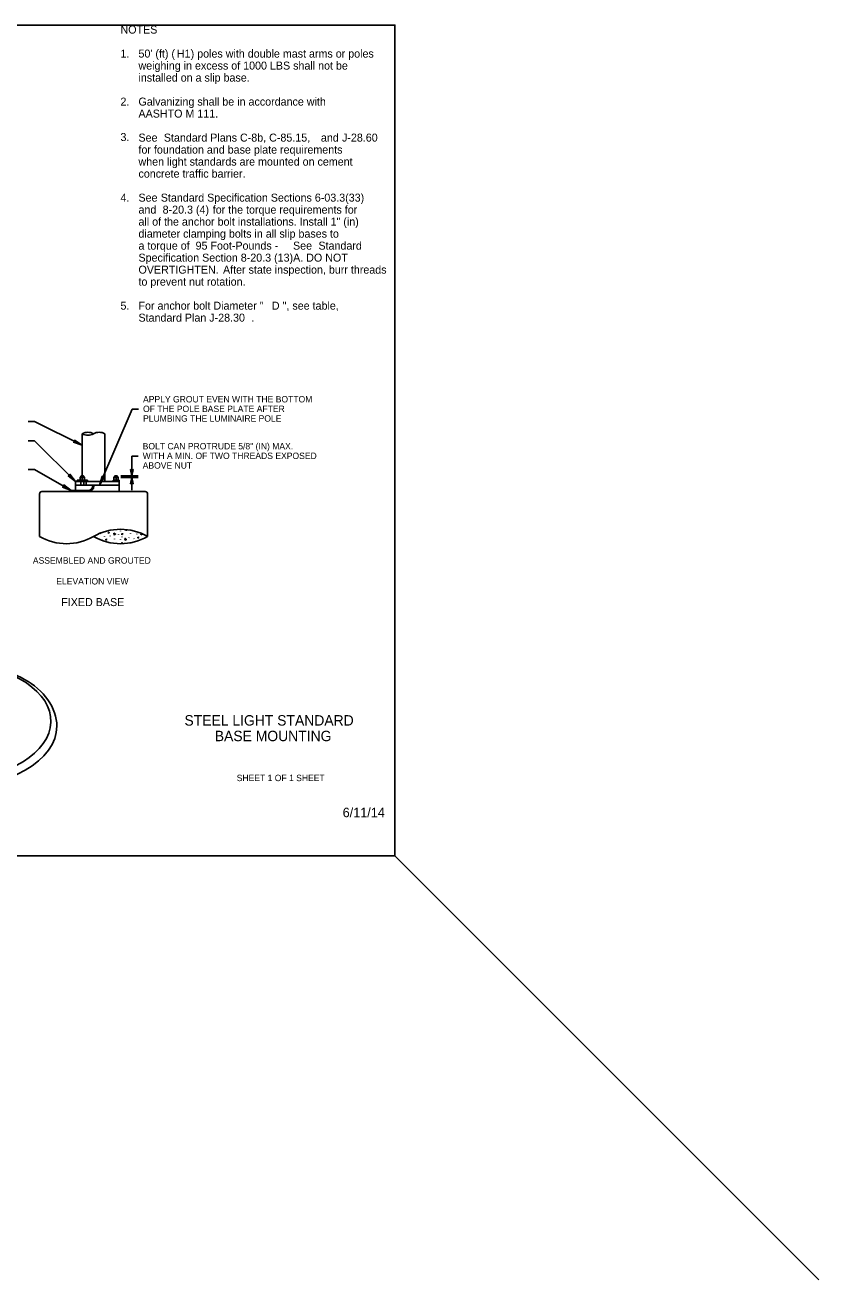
# Model space of a CAD drawing. Extents: x 99862 to 104211, y 98939 to 102076.
# Drawn here: x 102226 to 104211, y 98939 to 102076 of the extents above; entities that cross this region are included whole.
import ezdxf

# ---------------------------------------------------------------- set-up
doc = ezdxf.new("R2010")
doc.units = 0
for name, color, linetype in [('Level 1', 7, 'Continuous'), ('Level 11', 7, 'Continuous'), ('Level 12', 7, 'Continuous'), ('Level 15', 7, 'Continuous'), ('Level 16', 7, 'Continuous'), ('Level 20', 7, 'Continuous'), ('Level 60', 7, 'Continuous'), ('Level 62', 7, 'Continuous'), ('Level 7', 7, 'Continuous'), ('Level 8', 7, 'Continuous'), ('Level 9', 7, 'Continuous')]:
    doc.layers.add(name, color=color, linetype=linetype)

msp = doc.modelspace()

# ---------------------------------------------------------------- linework, layer by layer
at = {"layer": 'Level 1'}
msp.add_line((103150, 100000), (104210.7, 98939.3), dxfattribs=at)
msp.add_lwpolyline([(99862, 99999.5), (103151, 99999.5), (103151, 102075.5), (99862, 102075.5)], close=True, dxfattribs=at)
for centre, radius, start, end in [((102383.5, 101029.8), 28.1, 60, 120), ((102383.5, 101078.5), 28.1, 240, 300), ((102411.6, 101029.8), 28.1, 60, 120), ((102330, 100914.3), 135, 240, 300), ((102465, 100680.5), 135, 60, 120), ((102465, 100914.3), 135, 240, 300)]:
    msp.add_arc(centre, radius, start, end, dxfattribs=at)
at = {"layer": 'Level 11'}
for p, q in [((102356.7, 100934.7), (102356.7, 100938.4)), ((102356.7, 100938.4), (102374.6, 100938.4)), ((102356.7, 100934.7), (102374.6, 100934.7)), ((102374.6, 100938.4), (102382.1, 100938.4)), ((102374.6, 100934.7), (102374.6, 100938.4)), ((102374.6, 100934.7), (102375.2, 100934.7)), ((102382.1, 100934.7), (102382.1, 100938.4)), ((102446.3, 100938.4), (102461.3, 100938.4)), ((102446.3, 100934.7), (102446.3, 100938.4)), ((102461.3, 100934.7), (102461.3, 100938.4))]:
    msp.add_line(p, q, dxfattribs=at)
at = {"layer": 'Level 12'}
msp.add_lwpolyline([(102396.1, 100925.3), (102378.8, 100925.3), (102373.2, 100925.3), (102365.7, 100925.3), (102352.5, 100925.3), (102352.5, 100909.4), (102461.3, 100909.4), (102461.3, 100925.3), (102396.1, 100925.3)], dxfattribs=at)
for centre, major_axis, start_param, end_param in [((102035.9, 100335.8), (-255, 0), 4.934807, 10.773157), ((102035.9, 100323.6), (-270, 0), 6.283185, 9.424762)]:
    msp.add_ellipse(centre, major_axis=major_axis, ratio=0.57735, start_param=start_param, end_param=end_param, dxfattribs=at)
msp.add_open_spline([(102305.9, 100323.6), (102305.9, 100345.1), (102289.9, 100392.8), (102227.3, 100444.3), (102152.7, 100472), (102109.3, 100480.1), (102092.1, 100482.3)], degree=3, dxfattribs=at)
at = {"layer": 'Level 15'}
for p, q in [((102412.7, 100925.3), (102494.2, 101115.8)), ((102510.2, 101115.8), (102494.2, 101115.8)), ((102250.4, 101084.5), (102234.4, 101084.5)), ((102369.4, 101025.2), (102250.4, 101084.5)), ((102250.4, 101036.5), (102234.4, 101036.5)), ((102352.5, 100934.7), (102250.4, 101036.5)), ((102493.3, 100948.8), (102493.3, 100998.4)), ((102493.3, 100998.4), (102509.3, 100998.4)), ((102234.4, 100964.8), (102250.4, 100964.8)), ((102341.4, 100912.2), (102250.4, 100964.8)), ((102465.5, 100948.8), (102509.3, 100948.8)), ((102465.5, 100945), (102509.3, 100945)), ((102493.3, 100913), (102493.3, 100945))]:
    msp.add_line(p, q, dxfattribs=at)
for points in [[(102369.4, 101025.2), (102347.7, 101032.7), (102349.9, 101034.9), (102350.3, 101038)], [(102493.3, 100948.8), (102490.2, 100964.5), (102493.3, 100963.8), (102496.4, 100964.5)], [(102341.4, 100912.2), (102320.1, 100921), (102322.5, 100923.1), (102323.1, 100926.2)], [(102352.5, 100934.7), (102334.3, 100948.7), (102337.1, 100950.1), (102338.5, 100952.9)], [(102412.7, 100925.3), (102418.9, 100947.5), (102421.3, 100945.3), (102424.4, 100945.1)], [(102493.3, 100945), (102490.2, 100929.3), (102493.3, 100930), (102496.4, 100929.3)]]:
    msp.add_lwpolyline(points, close=True, dxfattribs=at)
at = {"layer": 'Level 16'}
for p, q in [((102425, 100796.8), (102425.1, 100797.7)), ((102439, 100797.8), (102439.1, 100798.7)), ((102459.7, 100802.6), (102460, 100801.8)), ((102465.2, 100810.7), (102465.3, 100811.6)), ((102468, 100796.9), (102468.5, 100796.5)), ((102468.4, 100796.8), (102468.9, 100796.4)), ((102479.2, 100811.6), (102479.3, 100812.5)), ((102490.2, 100804.5), (102490.3, 100805.4)), ((102505.4, 100802.8), (102505.5, 100803.7)), ((102419.4, 100788.7), (102419.8, 100788)), ((102446.1, 100781.1), (102446.1, 100781.1)), ((102450, 100790.7), (102450, 100791.6)), ((102465.2, 100789), (102465.3, 100789.8)), ((102486.2, 100794), (102486.3, 100794.9)), ((102498.5, 100792.3), (102499.1, 100791.9))]:
    msp.add_line(p, q, dxfattribs=at)
for points in [[(102415.5, 100805.7), (102414.2, 100804.7)], [(102414.2, 100804.7), (102414.2, 100805.2)], [(102434.6, 100805), (102434.9, 100807.4), (102437, 100806.8), (102434.6, 100805)], [(102449.5, 100800.4), (102448.5, 100805.5), (102452.6, 100803.4), (102449.6, 100800.5)], [(102468.5, 100801.9), (102468.7, 100804.4), (102470.8, 100803.7), (102468.5, 100801.9)], [(102515.9, 100801.7), (102516.4, 100805.1)], [(102519.7, 100803.5), (102519.8, 100803.4), (102515.9, 100801.7)], [(102428.2, 100788.1), (102428.5, 100790.5), (102430.6, 100789.8), (102428.2, 100788.1)], [(102467.9, 100779.7), (102468.2, 100781.7), (102470.3, 100781), (102468.6, 100779.8)], [(102475.6, 100787.9), (102476.4, 100792.9), (102479.6, 100789.6), (102475.7, 100787.9)], [(102488.6, 100781.8), (102488.6, 100782.1), (102489.2, 100781.9)], [(102508.1, 100793.1), (102508.4, 100795.6), (102510.5, 100794.9), (102508.1, 100793.1)], [(102528.8, 100795.5), (102528.9, 100795.9), (102529.4, 100795.7)]]:
    msp.add_lwpolyline(points, dxfattribs=at)
at = {"layer": 'Level 60'}
msp.add_line((103151, 102075.5), (103151, 102075.5), dxfattribs=at)
at = {"layer": 'Level 62'}
for points in [[(102366, 100934.7), (102365.7, 100934.7), (102365.6, 100934.6), (102365.7, 100934.6)], [(102365.7, 100947.1), (102365.7, 100947.1), (102365.7, 100947.1), (102365.7, 100947.1)], [(102365.7, 100945.9), (102365.7, 100945.9), (102365.7, 100945.9), (102365.7, 100945.8)]]:
    msp.add_open_spline(points, degree=3, dxfattribs=at)
at = {"layer": 'Level 7'}
for p, q in [((102356.1, 100934.7), (102356.7, 100934.7)), ((102375.2, 100934.7), (102378.8, 100934.7))]:
    msp.add_line(p, q, dxfattribs=at)
at = {"layer": 'Level 8'}
for p, q in [((102369.4, 101054.1), (102369.4, 100948.8)), ((102425.7, 100934.7), (102425.7, 101054.1)), ((102352.5, 100925.3), (102352.5, 100934.7)), ((102352.5, 100934.7), (102356.1, 100934.7)), ((102352.5, 100925.3), (102461.3, 100925.3)), ((102352.5, 100909.4), (102352.5, 100925.3)), ((102378.8, 100934.7), (102461.3, 100934.7)), ((102378.8, 100925.3), (102378.8, 100934.7)), ((102461.3, 100925.3), (102461.3, 100934.7)), ((102461.3, 100909.4), (102461.3, 100925.3)), ((102262.5, 100903.8), (102262.5, 100797.4)), ((102268.2, 100909.4), (102526.9, 100909.4)), ((102341.4, 100909.4), (102341.4, 100912.2)), ((102341.4, 100912.2), (102352.5, 100912.2)), ((102352.5, 100912.2), (102383, 100912.2)), ((102352.5, 100909.4), (102383, 100909.4)), ((102532.5, 100797.4), (102532.5, 100903.8))]:
    msp.add_line(p, q, dxfattribs=at)
for centre, radius, start, end in [((102383, 100925.3), 13.1, 270.0006, 360), ((102383, 100925.3), 15.9, 269.9997, 360), ((102268.2, 100903.8), 5.62, 90, 180), ((102526.9, 100903.8), 5.62, 0, 90)]:
    msp.add_arc(centre, radius, start, end, dxfattribs=at)
at = {"layer": 'Level 9'}
for p, q in [((102366.5, 100945), (102363.8, 100945)), ((102363.8, 100944.5), (102363.8, 100938.4)), ((102366.3, 100948.8), (102365.7, 100948.1)), ((102365.7, 100948.1), (102365.7, 100945)), ((102373.2, 100948.1), (102365.7, 100948.1)), ((102365.7, 100934.7), (102365.7, 100925.3)), ((102372.5, 100948.8), (102366.3, 100948.8)), ((102366.7, 100945), (102366.5, 100945)), ((102372.1, 100945), (102366.7, 100945)), ((102369.4, 100944.5), (102369.4, 100938.4)), ((102372.3, 100945), (102372.1, 100945)), ((102375, 100945), (102372.3, 100945)), ((102373.2, 100948.1), (102372.5, 100948.8)), ((102373.2, 100945), (102373.2, 100948.1)), ((102373.2, 100925.3), (102373.2, 100934.7)), ((102375, 100944.5), (102375, 100938.4)), ((102450.9, 100945), (102448.2, 100945)), ((102448.2, 100944.5), (102448.2, 100938.4)), ((102450.7, 100948.8), (102450, 100948.1)), ((102450, 100948.1), (102450, 100945)), ((102457.5, 100948.1), (102450, 100948.1)), ((102456.9, 100948.8), (102450.7, 100948.8)), ((102451.1, 100945), (102450.9, 100945)), ((102456.5, 100945), (102451.1, 100945)), ((102453.8, 100944.5), (102453.8, 100938.4)), ((102456.7, 100945), (102456.5, 100945)), ((102459.4, 100945), (102456.7, 100945)), ((102457.5, 100948.1), (102456.9, 100948.8)), ((102457.5, 100945), (102457.5, 100948.1)), ((102459.4, 100944.5), (102459.4, 100938.4))]:
    msp.add_line(p, q, dxfattribs=at)
for points in [[(102363.8, 100944.5), (102363.8, 100944.8), (102363.8, 100945), (102363.8, 100945)], [(102366.5, 100945), (102365.6, 100945), (102364.7, 100944.8), (102363.8, 100944.5)], [(102369.4, 100944.5), (102368.5, 100944.8), (102367.7, 100945), (102366.7, 100945)], [(102372.1, 100945), (102371.2, 100945), (102370.3, 100944.8), (102369.4, 100944.5)], [(102375, 100944.5), (102374.2, 100944.8), (102373.3, 100945), (102372.3, 100945)], [(102375, 100945), (102375, 100945), (102375, 100945), (102375, 100945)], [(102375, 100944.5), (102375, 100944.8), (102375, 100945), (102375, 100945)], [(102448.2, 100944.5), (102448.2, 100944.8), (102448.2, 100945), (102448.2, 100945)], [(102450.9, 100945), (102449.9, 100945), (102449, 100944.8), (102448.2, 100944.5)], [(102453.8, 100944.5), (102452.9, 100944.8), (102452, 100945), (102451.1, 100945)], [(102456.5, 100945), (102455.6, 100945), (102454.7, 100944.8), (102453.8, 100944.5)], [(102459.4, 100944.5), (102458.5, 100944.8), (102457.6, 100945), (102456.7, 100945)], [(102459.4, 100945), (102459.4, 100945), (102459.4, 100945), (102459.4, 100945)], [(102459.4, 100944.5), (102459.4, 100944.8), (102459.4, 100945), (102459.4, 100945)]]:
    msp.add_open_spline(points, degree=2, dxfattribs=at)

# ---------------------------------------------------------------- texts
at = {"layer": 'Level 1'}
msp.add_text('6/11/14', height=23.62, dxfattribs=at).set_placement((103020.3, 100095.8))
at = {"layer": 'Level 20'}
for s, height, p in [('NOTES', 20, (102464.9, 102054.3)), ('1.', 20, (102464.9, 101994.3)), ("50' (ft) (", 20, (102509.9, 101994.3)), ('H1', 20, (102605.6, 101994.3)), (') poles with double mast arms or poles', 20, (102640.3, 101994.3)), ('weighing in excess of 1000 LBS shall not be', 20, (102509.9, 101964.3)), ('installed on a slip base.', 20, (102509.9, 101934.3)), ('2.', 20, (102464.9, 101874.3)), ('Galvanizing shall be in accordance with', 20, (102509.9, 101874.3)), ('AASHTO M 111.', 20, (102509.9, 101844.3)), ('3.', 20, (102464.9, 101785.7)), ('See ', 20, (102509.9, 101784.3)), ('Standard Plans C-8b, C-85.15, ', 20, (102573.3, 101784.3)), ('and', 20, (102965.9, 101784.3)), (' J-28.60 ', 20, (103011.2, 101784.3)), ('for foundation and base plate requirements ', 20, (102509.9, 101754.3)), ('when light standards are mounted on cement ', 20, (102509.9, 101724.3)), ('concrete traffic barrier.', 20, (102509.9, 101694.3)), ('4.', 20, (102464.9, 101634.3)), ('See', 20, (102509.9, 101634.3)), (' Standard Specification Sections 6-03.3(33) ', 20, (102558.2, 101634.3)), ('and ', 20, (102509.9, 101604.3)), ('8-20.3 (4)', 20, (102570.3, 101604.3)), (' for the torque requirements for ', 20, (102688.1, 101604.3)), ('all of the anchor bolt installations. Install 1" (in) ', 20, (102509.9, 101574.3)), ('diameter clamping bolts in all slip bases to ', 20, (102509.9, 101544.3)), ('a torque of  95 Foot-Pounds - ', 20, (102509.9, 101514.3)), ('See ', 20, (102896.2, 101514.3)), ('Standard ', 20, (102959.7, 101514.3)), ('Specification Section 8-20.3 (13)A. DO NOT ', 20, (102509.9, 101484.3)), ('OVERTIGHTEN. ', 20, (102509.9, 101454.3)), ('After state inspection, burr threads ', 20, (102721.2, 101454.3)), ('to prevent nut rotation.', 20, (102509.9, 101424.3)), ('5.', 20, (102464.9, 101364.3)), ('For anchor bolt Diameter " ', 20, (102509.9, 101364.3)), ('D', 20, (102843.2, 101364.3)), (' ", see table,', 20, (102862.8, 101364.3)), ('Standard Plan J-28.30', 20, (102509.9, 101334.3)), ('.', 20, (102792.2, 101334.3)), ('ASSEMBLED AND GROUTED', 16, (102245.9, 100729.4)), ('ELEVATION VIEW', 16, (102304.4, 100677.4)), ('FIXED BASE', 20, (102316.8, 100623.4))]:
    msp.add_text(s, height=height, dxfattribs=at).set_placement(p)
for s, p in [('APPLY GROUT EVEN WITH THE BOTTOM', (102521.3, 101132.4)), ('OF THE POLE BASE PLATE AFTER', (102521.3, 101108.4)), ('PLUMBING THE LUMINAIRE POLE', (102521.3, 101084.4)), ('BOLT CAN PROTRUDE 5/8" (IN) MAX. ', (102520.4, 101015)), ('WITH A MIN. OF TWO THREADS EXPOSED ', (102520.4, 100991)), ('ABOVE NUT', (102520.4, 100967))]:
    msp.add_text(s, height=16, rotation=360, dxfattribs=at).set_placement(p)
at = {"layer": 'Level 62'}
for s, height, p in [('STEEL LIGHT STANDARD', 26, (102624.8, 100324.8)), ('BASE MOUNTING', 26, (102700.6, 100285.8)), ('SHEET 1 OF 1 SHEET', 16, (102755.4, 100185.9))]:
    msp.add_text(s, height=height, dxfattribs=at).set_placement(p)

doc.saveas('drawing.dxf')
